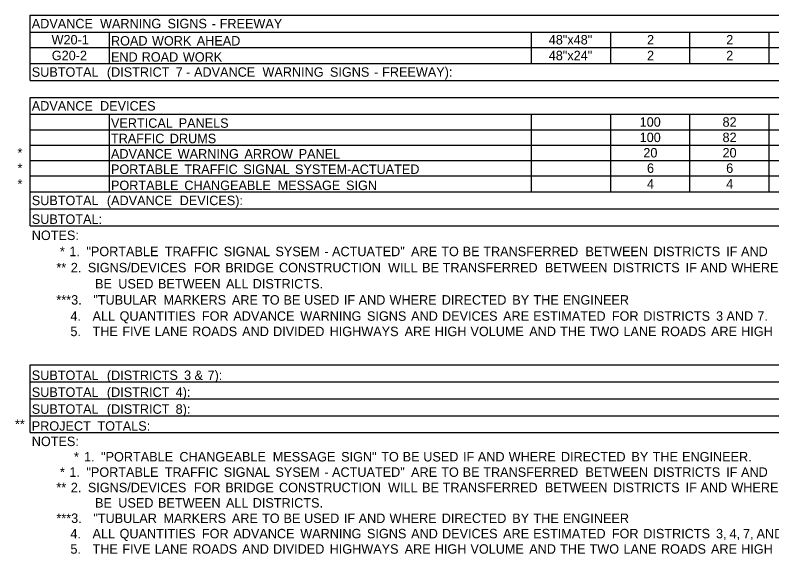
# Model space of a CAD drawing. Extents: x 540541 to 1930787, y -1948574 to 596640.
# Drawn here: x 544360.5 to 544840.3, y -1946859.8 to -1946518.2 of the extents above; entities that cross this region are included whole.
import ezdxf

# ---------------------------------------------------------------- set-up
doc = ezdxf.new("R2010")
doc.units = 0
doc.layers.add('Default', color=7, linetype='Continuous')

msp = doc.modelspace()

# ---------------------------------------------------------------- linework, layer by layer
at = {"layer": 'Default'}
for p, q in [((544370.09, -1946518.16), (545500.6, -1946518.16)), ((544370.09, -1946559.6), (544370.09, -1946518.16)), ((544370.09, -1946559.6), (544370.09, -1946518.16)), ((544420.3, -1946518.16), (545500.6, -1946518.16)), ((544370.09, -1946528.89), (545500.6, -1946528.89)), ((544420.3, -1946548.87), (544420.3, -1946528.89)), ((544420.3, -1946548.87), (544420.3, -1946528.89)), ((544687.94, -1946548.87), (544687.94, -1946528.89)), ((544687.94, -1946548.87), (544687.94, -1946528.89)), ((544738.15, -1946548.87), (544738.15, -1946528.89)), ((544738.15, -1946548.87), (544738.15, -1946528.89)), ((544788.36, -1946548.87), (544788.36, -1946528.89)), ((544788.36, -1946548.87), (544788.36, -1946528.89)), ((544838.58, -1946548.87), (544838.58, -1946528.89)), ((544838.58, -1946548.87), (544838.58, -1946528.89)), ((544370.09, -1946538.64), (545500.6, -1946538.64)), ((544370.09, -1946548.87), (545500.6, -1946548.87)), ((544370.09, -1946548.87), (544838.58, -1946548.87)), ((544370.09, -1946559.6), (545500.6, -1946559.6)), ((544370.09, -1946570.32), (545500.6, -1946570.32)), ((544370.09, -1946651.74), (544370.09, -1946570.32)), ((544370.09, -1946651.74), (544370.09, -1946570.32)), ((544370.09, -1946581.05), (545500.6, -1946581.05)), ((544420.3, -1946630.29), (544420.3, -1946581.05)), ((544420.3, -1946630.29), (544420.3, -1946581.05)), ((544687.94, -1946630.29), (544687.94, -1946581.05)), ((544687.94, -1946630.29), (544687.94, -1946581.05)), ((544738.15, -1946630.29), (544738.15, -1946581.05)), ((544738.15, -1946630.29), (544738.15, -1946581.05)), ((544788.36, -1946630.29), (544788.36, -1946581.05)), ((544788.36, -1946630.29), (544788.36, -1946581.05)), ((544838.58, -1946630.29), (544838.58, -1946581.05)), ((544838.58, -1946630.29), (544838.58, -1946581.05)), ((544370.09, -1946590.8), (545500.6, -1946590.8)), ((544370.09, -1946600.55), (545500.6, -1946600.55)), ((544370.09, -1946610.3), (545500.6, -1946610.3)), ((544370.09, -1946620.05), (545500.6, -1946620.05)), ((544370.09, -1946630.29), (545414.31, -1946630.29)), ((544370.09, -1946630.29), (545500.6, -1946630.29)), ((544370.09, -1946641.01), (545500.6, -1946641.01)), ((544370.09, -1946651.74), (545500.6, -1946651.74)), ((544370.09, -1946739.97), (544838.58, -1946739.97)), ((544370.09, -1946739.97), (544788.36, -1946739.97)), ((544370.09, -1946782.87), (544370.09, -1946739.97)), ((544370.09, -1946782.87), (544370.09, -1946739.97)), ((544788.36, -1946739.97), (545500.6, -1946739.97)), ((544370.09, -1946750.7), (545500.6, -1946750.7)), ((544370.09, -1946761.42), (545500.6, -1946761.42)), ((544370.09, -1946772.15), (545500.6, -1946772.15)), ((544370.09, -1946782.87), (545500.6, -1946782.87))]:
    msp.add_line(p, q, dxfattribs=at)

# ---------------------------------------------------------------- texts
for s, p in [('ADVANCE', (544371.06, -1946526.52)), (' WARNING', (544412.11, -1946526.52)), (' SIGNS', (544454.91, -1946526.52)), (' -', (544482.91, -1946526.52)), (' FREEWAY', (544487.97, -1946526.52)), ('W20-1', (544383.62, -1946536.76)), ('ROAD', (544421.28, -1946537.44)), (' WORK', (544445.05, -1946537.44)), (' AHEAD', (544473.44, -1946537.44)), ('48"x48"', (544698.85, -1946536.76)), ('2', (544761.15, -1946536.76)), ('2', (544811.36, -1946536.76)), ('G20-2', (544383.77, -1946546.76)), ('END', (544421.28, -1946547.67)), (' ROAD', (544438.53, -1946547.67)), (' WORK', (544464.63, -1946547.67)), ('48"x24"', (544698.85, -1946546.76)), ('2', (544761.15, -1946546.76)), ('2', (544811.36, -1946546.76)), ('SUBTOTAL', (544371.06, -1946557.24)), (' (DISTRICT', (544416.46, -1946557.24)), (' 7', (544460.06, -1946557.24)), (' ADVANCE', (544471.73, -1946557.24)), (' WARNING', (544515.1, -1946557.24)), (' SIGNS', (544557.9, -1946557.24)), (' FREEWAY):', (544590.97, -1946557.24)), (' -', (544466.67, -1946557.24)), (' -', (544585.91, -1946557.24)), ('ADVANCE', (544371.06, -1946578.69)), (' DEVICES', (544412.11, -1946578.69)), ('VERTICAL', (544421.28, -1946589.6)), (' PANELS', (544461.98, -1946589.6)), ('100', (544756.47, -1946588.92)), ('82', (544809.03, -1946588.92)), ('TRAFFIC', (544421.28, -1946599.35)), (' DRUMS', (544456.34, -1946599.35)), ('100', (544756.47, -1946598.67)), ('82', (544809.03, -1946598.67)), ('*', (544362.02, -1946608.42)), ('ADVANCE', (544421.28, -1946609.1)), (' WARNING', (544461.36, -1946609.1)), (' ARROW', (544503.68, -1946609.1)), (' PANEL', (544538.05, -1946609.1)), ('20', (544758.8, -1946608.42)), ('20', (544809.01, -1946608.42)), ('*', (544362.02, -1946618.17)), ('PORTABLE', (544421.28, -1946618.85)), (' TRAFFIC', (544465.56, -1946618.85)), (' SIGNAL', (544502.95, -1946618.85)), (' SYSTEM-ACTUATED', (544535.73, -1946618.85)), ('6', (544761.12, -1946618.17)), ('6', (544811.33, -1946618.17)), ('*', (544362.02, -1946628.17)), ('PORTABLE', (544421.28, -1946629.09)), (' CHANGEABLE', (544465.56, -1946629.09)), (' MESSAGE', (544524.75, -1946629.09)), (' SIGN', (544568.1, -1946629.09)), ('4', (544761.13, -1946628.17)), ('4', (544811.34, -1946628.17)), ('SUBTOTAL', (544371.06, -1946638.65)), (' (ADVANCE', (544416.46, -1946638.65)), (' DEVICES):', (544462.62, -1946638.65)), ('SUBTOTAL:', (544371.06, -1946650.54)), ('NOTES:', (544371.06, -1946660.77)), ('        *', (544371.06, -1946671.01)), (' 1.', (544392.65, -1946671.01)), ('  "PORTABLE', (544401.24, -1946671.01)), (' TRAFFIC', (544453.15, -1946671.01)), (' SIGNAL', (544490.54, -1946671.01)), (' SYSEM', (544523.32, -1946671.01)), (' -', (544554.37, -1946671.01)), (' ACTUATED"', (544559.23, -1946671.01)), (' ARE', (544609.33, -1946671.01)), (' TO', (544628.45, -1946671.01)), (' BE', (544642.05, -1946671.01)), (' TRANSFERRED', (544655.11, -1946671.01)), (' BETWEEN', (544719.88, -1946671.01)), (' DISTRICTS', (544762.98, -1946671.01)), (' IF', (544809.12, -1946671.01)), (' AND', (544818.52, -1946671.01)), ('       **', (544371.06, -1946681.25)), (' 2.', (544393.59, -1946681.25)), ('  SIGNS/DEVICES', (544402.17, -1946681.25)), (' FOR', (544471.61, -1946681.25)), (' BRIDGE', (544491.53, -1946681.25)), (' CONSTRUCTION', (544525.55, -1946681.25)), (' WILL', (544594.73, -1946681.25)), (' BE', (544616.32, -1946681.25)), (' TRANSFERRED', (544629.38, -1946681.25)), (' BETWEEN', (544694.15, -1946681.25)), (' DISTRICTS', (544737.26, -1946681.25)), (' IF', (544783.39, -1946681.25)), (' AND', (544792.79, -1946681.25)), (' WHERE', (544812.37, -1946681.25)), ('                  BE', (544371.06, -1946691.49)), (' USED', (544423.7, -1946691.49)), (' BETWEEN', (544448.88, -1946691.49)), (' ALL', (544491.98, -1946691.49)), (' DISTRICTS.', (544508.92, -1946691.49)), ('       ***3.', (544371.06, -1946701.72)), ('   "TUBULAR', (544403.4, -1946701.72)), (' MARKERS', (544452.37, -1946701.72)), (' ARE', (544495.73, -1946701.72)), (' TO', (544514.85, -1946701.72)), (' BE', (544528.44, -1946701.72)), (' USED', (544541.51, -1946701.72)), (' IF', (544566.69, -1946701.72)), (' AND', (544576.08, -1946701.72)), (' WHERE', (544595.66, -1946701.72)), (' DIRECTED', (544628.75, -1946701.72)), (' BY', (544673.48, -1946701.72)), (' THE', (544686.93, -1946701.72)), (' ENGINEER', (544705.58, -1946701.72)), ('           4.', (544371.06, -1946711.96)), ('   ALL', (544402.92, -1946711.96)), (' QUANTITIES', (544424.52, -1946711.96)), (' FOR', (544476.72, -1946711.96)), (' ADVANCE', (544496.63, -1946711.96)), (' WARNING', (544539.05, -1946711.96)), (' SIGNS', (544581.37, -1946711.96)), (' AND', (544609.35, -1946711.96)), (' DEVICES', (544628.93, -1946711.96)), (' ARE', (544667.63, -1946711.96)), (' ESTIMATED', (544686.75, -1946711.96)), (' FOR', (544736.61, -1946711.96)), (' DISTRICTS', (544756.52, -1946711.96)), (' 3', (544802.66, -1946711.96)), (' AND', (544809.27, -1946711.96)), (' 7.', (544828.85, -1946711.96)), ('           5.', (544371.06, -1946721.71)), ('   THE', (544402.92, -1946721.71)), (' FIVE', (544426.23, -1946721.71)), (' LANE', (544446.74, -1946721.71)), (' ROADS', (544470.53, -1946721.71)), (' AND', (544502.23, -1946721.71)), (' DIVIDED', (544521.81, -1946721.71)), (' HIGHWAYS', (544557.7, -1946721.71)), (' ARE', (544605.24, -1946721.71)), (' HIGH', (544624.36, -1946721.71)), (' VOLUME', (544646.97, -1946721.71)), (' AND', (544684.25, -1946721.71)), (' THE', (544703.83, -1946721.71)), (' TWO', (544722.48, -1946721.71)), (' LANE', (544743.99, -1946721.71)), (' ROADS', (544767.77, -1946721.71)), (' ARE', (544799.48, -1946721.71)), (' HIGH', (544818.6, -1946721.71)), ('SUBTOTAL', (544371.06, -1946749.5)), (' (DISTRICTS', (544416.46, -1946749.5)), (' 3', (544465.41, -1946749.5)), (' &', (544472.04, -1946749.5)), (' 7):', (544480.28, -1946749.5)), ('SUBTOTAL', (544371.06, -1946760.22)), (' (DISTRICT', (544416.46, -1946760.22)), (' 4):', (544460.06, -1946760.22)), ('SUBTOTAL', (544371.06, -1946770.95)), (' (DISTRICT', (544416.46, -1946770.95)), (' 8):', (544460.06, -1946770.95)), ('**', (544360.39, -1946780.51)), ('PROJECT', (544371.06, -1946781.67)), (' TOTALS:', (544410.49, -1946781.67)), ('NOTES:', (544371.06, -1946791.42)), ('            *', (544371.06, -1946801.17)), (' 1.', (544401.96, -1946801.17)), ('  "PORTABLE', (544410.55, -1946801.17)), (' CHANGEABLE', (544462.46, -1946801.17)), (' MESSAGE', (544521.65, -1946801.17)), (' SIGN"', (544565, -1946801.17)), (' TO', (544590.41, -1946801.17)), (' BE', (544604.01, -1946801.17)), (' USED', (544617.07, -1946801.17)), (' IF', (544642.25, -1946801.17)), (' AND', (544651.64, -1946801.17)), (' WHERE', (544671.22, -1946801.17)), (' DIRECTED', (544704.31, -1946801.17)), (' BY', (544749.04, -1946801.17)), (' THE', (544762.49, -1946801.17)), (' ENGINEER.', (544781.14, -1946801.17)), ('        *', (544371.06, -1946810.92)), (' 1.', (544392.65, -1946810.92)), ('  "PORTABLE', (544401.24, -1946810.92)), (' TRAFFIC', (544453.15, -1946810.92)), (' SIGNAL', (544490.54, -1946810.92)), (' SYSEM', (544523.32, -1946810.92)), (' ACTUATED"', (544559.23, -1946810.92)), (' ARE', (544609.33, -1946810.92)), (' TO', (544628.45, -1946810.92)), (' BE', (544642.05, -1946810.92)), (' TRANSFERRED', (544655.11, -1946810.92)), (' BETWEEN', (544719.88, -1946810.92)), (' DISTRICTS', (544762.98, -1946810.92)), (' IF', (544809.12, -1946810.92)), (' AND', (544818.52, -1946810.92)), (' -', (544554.37, -1946810.92)), ('       **', (544371.06, -1946820.67)), (' 2.', (544393.59, -1946820.67)), ('  SIGNS/DEVICES', (544402.17, -1946820.67)), (' FOR', (544471.61, -1946820.67)), (' BRIDGE', (544491.53, -1946820.67)), (' CONSTRUCTION', (544525.55, -1946820.67)), (' WILL', (544594.73, -1946820.67)), (' BE', (544616.32, -1946820.67)), (' TRANSFERRED', (544629.38, -1946820.67)), (' BETWEEN', (544694.15, -1946820.67)), (' DISTRICTS', (544737.26, -1946820.67)), (' IF', (544783.39, -1946820.67)), (' AND', (544792.79, -1946820.67)), (' WHERE', (544812.37, -1946820.67)), ('                  BE', (544371.06, -1946830.42)), (' USED', (544423.7, -1946830.42)), (' BETWEEN', (544448.88, -1946830.42)), (' ALL', (544491.98, -1946830.42)), (' DISTRICTS.', (544508.92, -1946830.42)), ('       ***3.', (544371.06, -1946840.17)), ('   "TUBULAR', (544403.4, -1946840.17)), (' MARKERS', (544452.37, -1946840.17)), (' ARE', (544495.73, -1946840.17)), (' TO', (544514.85, -1946840.17)), (' BE', (544528.44, -1946840.17)), (' USED', (544541.51, -1946840.17)), (' IF', (544566.69, -1946840.17)), (' AND', (544576.08, -1946840.17)), (' WHERE', (544595.66, -1946840.17)), (' DIRECTED', (544628.75, -1946840.17)), (' BY', (544673.48, -1946840.17)), (' THE', (544686.93, -1946840.17)), (' ENGINEER', (544705.58, -1946840.17)), ('           4.', (544371.06, -1946849.92)), ('   ALL', (544402.92, -1946849.92)), (' QUANTITIES', (544424.52, -1946849.92)), (' FOR', (544476.72, -1946849.92)), (' ADVANCE', (544496.63, -1946849.92)), (' WARNING', (544539.05, -1946849.92)), (' SIGNS', (544581.37, -1946849.92)), (' AND', (544609.35, -1946849.92)), (' DEVICES', (544628.93, -1946849.92)), (' ARE', (544667.63, -1946849.92)), (' ESTIMATED', (544686.75, -1946849.92)), (' FOR', (544736.61, -1946849.92)), (' DISTRICTS', (544756.52, -1946849.92)), (' 3,', (544802.66, -1946849.92)), (' 4,', (544811.23, -1946849.92)), (' 7,', (544819.8, -1946849.92)), (' AND', (544828.37, -1946849.92)), ('           5.', (544371.06, -1946859.67)), ('   THE', (544402.92, -1946859.67)), (' FIVE', (544426.23, -1946859.67)), (' LANE', (544446.74, -1946859.67)), (' ROADS', (544470.53, -1946859.67)), (' AND', (544502.23, -1946859.67)), (' DIVIDED', (544521.81, -1946859.67)), (' HIGHWAYS', (544557.7, -1946859.67)), (' ARE', (544605.24, -1946859.67)), (' HIGH', (544624.36, -1946859.67)), (' VOLUME', (544646.97, -1946859.67)), (' AND', (544684.25, -1946859.67)), (' THE', (544703.83, -1946859.67)), (' TWO', (544722.48, -1946859.67)), (' LANE', (544743.99, -1946859.67)), (' ROADS', (544767.77, -1946859.67)), (' ARE', (544799.48, -1946859.67)), (' HIGH', (544818.6, -1946859.67))]:
    msp.add_text(s, height=6, dxfattribs=at).set_placement(p)

doc.saveas('drawing.dxf')
